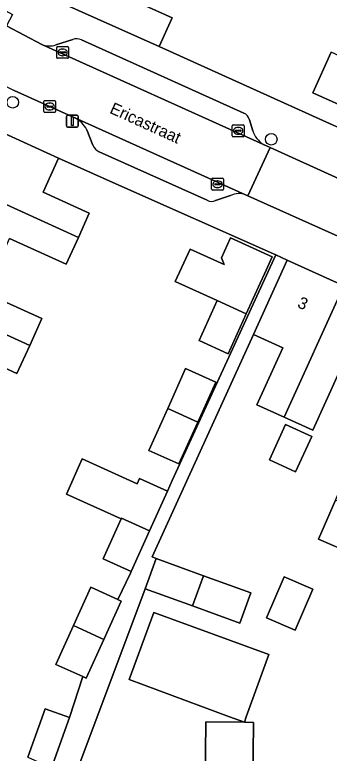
# Model space of a CAD drawing. Extents: x 161838 to 162344, y 381620 to 382160.
# Drawn here: x 162082.2 to 162108.9, y 381684.5 to 381747 of the extents above; entities that cross this region are included whole.
import ezdxf

# ---------------------------------------------------------------- set-up
doc = ezdxf.new("R2010")
doc.units = 0
for name, color, linetype in [('IMGEO_Boom', 7, 'Continuous'), ('IMGEO_Erf', 7, 'Continuous'), ('IMGEO_Kolk', 7, 'Continuous'), ('IMGEO_Lichtmast', 7, 'Continuous'), ('IMGEO_Muur', 7, 'Continuous'), ('IMGEO_Openbare_ruimte_label', 7, 'Continuous'), ('IMGEO_Pand', 7, 'Continuous'), ('IMGEO_Pand_nummerreeks', 7, 'Continuous'), ('IMGEO_Parkeervlak_open', 7, 'Continuous'), ('IMGEO_Rijbaan_lokaal_open', 7, 'Continuous'), ('IMGEO_Voetpad_open', 7, 'Continuous')]:
    doc.layers.add(name, color=color, linetype=linetype)

msp = doc.modelspace()

# ---------------------------------------------------------------- linework, layer by layer
at = {"layer": 'IMGEO_Boom'}
for centre in [(162082.036, 381739.628), (162103.955, 381736.494)]:
    msp.add_circle(centre, 0.489, dxfattribs=at)
at = {"layer": 'IMGEO_Erf'}
for points in [[(162090.511, 381749.074), (162095.561, 381746.795), (162094.462, 381744.361), (162109.199, 381737.693)], [(162109.937, 381739.317), (162107.478, 381740.434), (162109.029, 381743.87)], [(162088.658, 381698.548), (162090.95, 381697.511), (162092.017, 381699.75), (162092.078, 381699.884), (162089.708, 381700.955), (162089.797, 381701.152), (162091.243, 381704.348), (162086.595, 381706.452), (162087.939, 381709.423), (162092.588, 381707.32), (162092.79, 381707.767), (162095.158, 381706.695), (162095.567, 381707.599), (162104.332, 381726.702), (162104.139, 381726.788), (162090.772, 381732.737), (162085.927, 381734.893), (162084.615, 381732.008), (162088.528, 381730.228), (162087.601, 381728.189), (162086.563, 381725.907), (162081.771, 381728.087)], [(162079.684, 381723.498), (162084.511, 381721.303), (162083.477, 381719.029), (162082.393, 381716.646), (162077.551, 381718.849)], [(162109.694, 381716.716), (162107.482, 381711.859), (162105.035, 381712.973), (162102.742, 381714.018), (162104.938, 381718.838), (162102.44, 381719.975), (162093.858, 381701.12), (162094.204, 381700.994), (162098.21, 381699.535), (162102.216, 381698.076), (162101.28, 381695.508), (162097.275, 381696.967), (162093.269, 381698.426), (162082.012, 381668.432)], [(162083.331, 381684.161), (162084.79, 381688.265), (162086.856, 381687.521), (162087.984, 381690.984), (162085.701, 381692.017), (162087.188, 381695.302), (162088.658, 381698.548)]]:
    msp.add_lwpolyline(points, dxfattribs=at)
for points in [[(162095.816, 381724.45), (162097.067, 381727.201), (162099.956, 381725.888), (162099.736, 381726.467), (162100.504, 381728.155), (162104.03, 381726.549), (162103.369, 381725.098), (162103.005, 381724.3), (162101.828, 381721.716), (162100.289, 381718.336), (162097.831, 381719.455), (162099.37, 381722.834)], [(162096.693, 381717.076), (162099.246, 381715.924), (162097.723, 381712.549), (162096.119, 381708.994), (162093.567, 381710.146), (162095.174, 381713.708)], [(162106.017, 381708.325), (162103.793, 381709.339), (162105.159, 381712.334), (162107.383, 381711.32)], [(162110.415, 381701.575), (162110.06, 381701.727), (162107.97, 381702.62), (162109.385, 381705.932), (162110.896, 381709.468), (162113.341, 381708.423), (162111.809, 381704.837)], [(162105.979, 381694.913), (162103.552, 381695.95), (162105.041, 381699.434), (162107.468, 381698.397)], [(162101.674, 381687.113), (162100.414, 381687.58), (162091.922, 381690.727), (162093.988, 381696.402), (162103.741, 381692.849), (162101.838, 381687.567)], [(162102.347, 381676.631), (162102.339, 381675.747), (162105.346, 381675.721), (162105.285, 381668.74), (162102.278, 381668.767), (162102.257, 381666.35), (162101.562, 381666.356), (162098.216, 381666.386), (162098.219, 381666.785), (162098.299, 381675.783), (162098.306, 381676.667), (162098.398, 381687.142), (162101.674, 381687.113), (162102.439, 381687.106)]]:
    msp.add_lwpolyline(points, close=True, dxfattribs=at)
at = {"layer": 'IMGEO_Kolk'}
for p, q in [((162085.765, 381743.43), (162085.765, 381744.282)), ((162085.84, 381744.356), (162086.692, 381744.356)), ((162086.024, 381743.85), (162086.024, 381743.862)), ((162086.462, 381743.813), (162086.064, 381743.813)), ((162086.067, 381743.899), (162086.465, 381743.899)), ((162086.253, 381744.136), (162086.278, 381744.136)), ((162086.508, 381743.862), (162086.508, 381743.85)), ((162086.766, 381744.282), (162086.766, 381743.43)), ((162086.692, 381743.356), (162085.84, 381743.356)), ((162086.276, 381743.576), (162086.251, 381743.576)), ((162084.671, 381738.846), (162084.671, 381739.698)), ((162084.746, 381739.772), (162085.598, 381739.772)), ((162085.159, 381739.552), (162085.184, 381739.552)), ((162085.672, 381739.698), (162085.672, 381738.846)), ((162084.93, 381739.266), (162084.93, 381739.278)), ((162085.368, 381739.229), (162084.97, 381739.229)), ((162084.973, 381739.315), (162085.371, 381739.315)), ((162085.182, 381738.992), (162085.157, 381738.992)), ((162085.414, 381739.278), (162085.414, 381739.266)), ((162085.598, 381738.772), (162084.746, 381738.772)), ((162100.652, 381736.787), (162100.652, 381737.639)), ((162100.727, 381737.713), (162101.579, 381737.713)), ((162101.653, 381737.639), (162101.653, 381736.787)), ((162100.911, 381737.207), (162100.911, 381737.219)), ((162101.349, 381737.17), (162100.951, 381737.17)), ((162100.954, 381737.256), (162101.352, 381737.256)), ((162101.163, 381736.933), (162101.138, 381736.933)), ((162101.14, 381737.493), (162101.165, 381737.493)), ((162101.395, 381737.219), (162101.395, 381737.207)), ((162101.579, 381736.713), (162100.727, 381736.713)), ((162098.977, 381733.192), (162099.829, 381733.192)), ((162098.902, 381732.266), (162098.902, 381733.118)), ((162099.161, 381732.686), (162099.161, 381732.698)), ((162099.599, 381732.649), (162099.201, 381732.649)), ((162099.204, 381732.735), (162099.602, 381732.735)), ((162099.39, 381732.972), (162099.415, 381732.972)), ((162099.645, 381732.698), (162099.645, 381732.686)), ((162099.903, 381733.118), (162099.903, 381732.266)), ((162099.829, 381732.192), (162098.977, 381732.192)), ((162099.413, 381732.412), (162099.388, 381732.412))]:
    msp.add_line(p, q, dxfattribs=at)
for points in [[(162085.765, 381743.43), (162085.765, 381744.282)], [(162085.84, 381744.356), (162086.692, 381744.356)], [(162086.766, 381744.282), (162086.766, 381743.43)], [(162086.692, 381743.356), (162085.84, 381743.356)], [(162084.671, 381738.846), (162084.671, 381739.698)], [(162084.746, 381739.772), (162085.598, 381739.772)], [(162085.672, 381739.698), (162085.672, 381738.846)], [(162085.598, 381738.772), (162084.746, 381738.772)], [(162100.652, 381736.787), (162100.652, 381737.639)], [(162100.727, 381737.713), (162101.579, 381737.713)], [(162101.653, 381737.639), (162101.653, 381736.787)], [(162101.579, 381736.713), (162100.727, 381736.713)], [(162098.977, 381733.192), (162099.829, 381733.192)], [(162098.902, 381732.266), (162098.902, 381733.118)], [(162099.903, 381733.118), (162099.903, 381732.266)], [(162099.829, 381732.192), (162098.977, 381732.192)]]:
    msp.add_lwpolyline(points, dxfattribs=at)
for centre, radius, start, end in [((162085.842, 381744.28), 0.0765, 91.55205, 178.44795), ((162085.842, 381744.28), 0.0765, 91.55205, 178.44795), ((162086.064, 381743.859), 0.0403, 85.87752, 175.75265), ((162086.061, 381743.849), 0.0366, 178.93798, 274.71019), ((162086.465, 381743.856), 0.043, 264.86636, 352.45326), ((162086.469, 381743.861), 0.0386, 1.73085, 96.63898), ((162086.69, 381744.28), 0.0765, 1.55205, 88.44795), ((162086.69, 381744.28), 0.0765, 1.55205, 88.44795), ((162085.842, 381743.432), 0.0765, 181.55205, 268.44795), ((162085.842, 381743.432), 0.0765, 181.55205, 268.44795), ((162086.69, 381743.432), 0.0765, 271.55205, 358.44795), ((162086.69, 381743.432), 0.0765, 271.55205, 358.44795), ((162084.748, 381739.696), 0.0765, 91.55205, 178.44795), ((162084.748, 381739.696), 0.0765, 91.55205, 178.44795), ((162085.596, 381739.696), 0.0765, 1.55205, 88.44795), ((162085.596, 381739.696), 0.0765, 1.55205, 88.44795), ((162084.748, 381738.848), 0.0765, 181.55205, 268.44795), ((162084.748, 381738.848), 0.0765, 181.55205, 268.44795), ((162084.97, 381739.275), 0.0403, 85.87752, 175.75265), ((162084.967, 381739.265), 0.0366, 178.93798, 274.71019), ((162085.371, 381739.272), 0.043, 264.86636, 352.45326), ((162085.375, 381739.277), 0.0386, 1.73085, 96.63898), ((162085.596, 381738.848), 0.0765, 271.55205, 358.44795), ((162085.596, 381738.848), 0.0765, 271.55205, 358.44795), ((162100.729, 381737.637), 0.0765, 91.55205, 178.44795), ((162100.729, 381737.637), 0.0765, 91.55205, 178.44795), ((162101.577, 381737.637), 0.0765, 1.55205, 88.44795), ((162101.577, 381737.637), 0.0765, 1.55205, 88.44795), ((162100.951, 381737.216), 0.0403, 85.87752, 175.75265), ((162100.948, 381737.206), 0.0366, 178.93798, 274.71019), ((162101.352, 381737.213), 0.043, 264.86636, 352.45326), ((162101.356, 381737.218), 0.0386, 1.73085, 96.63898), ((162100.729, 381736.789), 0.0765, 181.55205, 268.44795), ((162100.729, 381736.789), 0.0765, 181.55205, 268.44795), ((162101.577, 381736.789), 0.0765, 271.55205, 358.44795), ((162101.577, 381736.789), 0.0765, 271.55205, 358.44795), ((162098.979, 381733.116), 0.0765, 91.55205, 178.44795), ((162098.979, 381733.116), 0.0765, 91.55205, 178.44795), ((162099.827, 381733.116), 0.0765, 1.55205, 88.44795), ((162099.827, 381733.116), 0.0765, 1.55205, 88.44795), ((162099.201, 381732.695), 0.0403, 85.87752, 175.75265), ((162099.198, 381732.685), 0.0366, 178.93798, 274.71019), ((162099.602, 381732.692), 0.043, 264.86636, 352.45326), ((162099.606, 381732.697), 0.0386, 1.73085, 96.63898), ((162098.979, 381732.268), 0.0765, 181.55205, 268.44795), ((162098.979, 381732.268), 0.0765, 181.55205, 268.44795), ((162099.827, 381732.268), 0.0765, 271.55205, 358.44795), ((162099.827, 381732.268), 0.0765, 271.55205, 358.44795)]:
    msp.add_arc(centre, radius, start, end, dxfattribs=at)
for centre, major_axis, ratio, start_param, end_param in [((162086.252, 381743.856), (-0.387, 0.002), 0.722429, 4.712389, 7.853982), ((162086.277, 381743.856), (-0.39, 0.002), 0.717154, 1.570796, 4.712389), ((162085.158, 381739.272), (-0.387, 0.002), 0.722429, 4.712389, 7.853982), ((162085.183, 381739.272), (-0.39, 0.002), 0.717154, 1.570796, 4.712389), ((162101.139, 381737.213), (-0.387, 0.002), 0.722429, 4.712389, 7.853982), ((162101.164, 381737.213), (-0.39, 0.002), 0.717154, 1.570796, 4.712389), ((162099.389, 381732.692), (-0.387, 0.002), 0.722429, 4.712389, 7.853982), ((162099.414, 381732.692), (-0.39, 0.002), 0.717154, 1.570796, 4.712389)]:
    msp.add_ellipse(centre, major_axis=major_axis, ratio=ratio, start_param=start_param, end_param=end_param, dxfattribs=at)
at = {"layer": 'IMGEO_Lichtmast'}
for p, q in [((162086.589, 381737.631), (162086.589, 381738.431)), ((162086.589, 381738.431), (162086.589, 381737.631)), ((162086.689, 381738.531), (162087.479, 381738.531)), ((162087.479, 381738.531), (162086.689, 381738.531)), ((162087.579, 381738.431), (162087.579, 381737.631)), ((162087.579, 381737.631), (162087.579, 381738.431)), ((162087.479, 381737.531), (162086.689, 381737.531)), ((162086.689, 381737.531), (162087.479, 381737.531))]:
    msp.add_line(p, q, dxfattribs=at)
msp.add_lwpolyline([(162087.009, 381738.406), (162087.159, 381738.406), (162087.159, 381737.656), (162087.009, 381737.656), (162087.009, 381738.406)], dxfattribs=at)
for centre, start, end in [((162086.689, 381738.431), 90, 180), ((162086.689, 381738.431), 90, 180), ((162087.479, 381738.431), 0, 90), ((162087.479, 381738.431), 360, 90), ((162086.689, 381737.631), 180, 270), ((162086.689, 381737.631), 180, 270), ((162087.479, 381737.631), 270, 0), ((162087.479, 381737.631), 270, 0)]:
    msp.add_arc(centre, 0.1, start, end, dxfattribs=at)
at = {"layer": 'IMGEO_Muur'}
for points in [[(162094.462, 381744.361), (162109.441, 381737.584)], [(162085.927, 381734.893), (162090.772, 381732.737)], [(162090.772, 381732.737), (162104.139, 381726.788)]]:
    msp.add_lwpolyline(points, dxfattribs=at)
at = {"layer": 'IMGEO_Pand'}
for points in [[(162091.62, 381751.529), (162085.748, 381754.149), (162083.874, 381750), (162083.788, 381749.81), (162086.038, 381748.793), (162085.784, 381748.23), (162094.462, 381744.361), (162095.561, 381746.795), (162090.511, 381749.074), (162090.929, 381750)], [(162109.937, 381739.317), (162111.487, 381742.753), (162109.029, 381743.87), (162107.478, 381740.434)], [(162087.601, 381728.189), (162088.528, 381730.228), (162084.615, 381732.008), (162085.927, 381734.893), (162080.942, 381737.161), (162080.663, 381736.548), (162078.267, 381737.638), (162076.306, 381733.328)], [(162087.601, 381728.189), (162076.306, 381733.328), (162074.208, 381728.716), (162080.711, 381725.757), (162081.771, 381728.087), (162086.563, 381725.907)], [(162072.147, 381724.183), (162083.477, 381719.029), (162084.511, 381721.303), (162079.684, 381723.498), (162080.711, 381725.757), (162074.208, 381728.716)], [(162103.369, 381725.098), (162104.03, 381726.549), (162100.504, 381728.155), (162099.736, 381726.467), (162099.956, 381725.888), (162097.067, 381727.201), (162095.816, 381724.45), (162099.37, 381722.834), (162101.828, 381721.716), (162103.005, 381724.3)], [(162105.035, 381712.973), (162110.102, 381724.084), (162105.307, 381726.268), (162103.234, 381721.718), (162102.44, 381719.975), (162104.938, 381718.838), (162102.742, 381714.018)], [(162072.147, 381724.183), (162070.06, 381719.595), (162076.547, 381716.643), (162077.551, 381718.849), (162082.393, 381716.646), (162083.477, 381719.029)], [(162105.035, 381712.973), (162107.482, 381711.859), (162109.694, 381716.716), (162112.052, 381715.642), (162112.829, 381717.348), (162114.846, 381721.774), (162114.902, 381721.897), (162110.102, 381724.084)], [(162101.828, 381721.716), (162099.37, 381722.834), (162097.831, 381719.455), (162100.289, 381718.336)], [(162095.174, 381713.708), (162097.723, 381712.549), (162099.246, 381715.924), (162096.693, 381717.076)], [(162095.174, 381713.708), (162093.567, 381710.146), (162096.119, 381708.994), (162097.723, 381712.549)], [(162103.793, 381709.339), (162106.017, 381708.325), (162107.383, 381711.32), (162105.159, 381712.334)], [(162095.158, 381706.695), (162092.79, 381707.767), (162092.588, 381707.32), (162087.939, 381709.423), (162086.595, 381706.452), (162091.243, 381704.348), (162091.266, 381704.399), (162093.633, 381703.323)], [(162111.809, 381704.837), (162111.457, 381704.996), (162110.669, 381705.352), (162109.385, 381705.932), (162107.97, 381702.62), (162110.06, 381701.727), (162110.415, 381701.575)], [(162093.633, 381703.323), (162091.266, 381704.399), (162091.243, 381704.348), (162089.797, 381701.152), (162089.708, 381700.955), (162092.078, 381699.884)], [(162097.275, 381696.967), (162098.21, 381699.535), (162094.204, 381700.994), (162093.269, 381698.426)], [(162097.275, 381696.967), (162101.28, 381695.508), (162102.216, 381698.076), (162098.21, 381699.535)], [(162103.552, 381695.95), (162105.979, 381694.913), (162107.468, 381698.397), (162105.041, 381699.434)], [(162090.95, 381697.511), (162088.658, 381698.548), (162087.188, 381695.302), (162089.029, 381694.464), (162089.5, 381694.25), (162089.758, 381694.133), (162091.229, 381697.385), (162091.125, 381697.432), (162090.97, 381697.502)], [(162091.922, 381690.727), (162100.414, 381687.58), (162101.674, 381687.113), (162101.838, 381687.567), (162103.741, 381692.849), (162093.988, 381696.402)], [(162089.758, 381694.133), (162089.5, 381694.25), (162089.029, 381694.464), (162087.188, 381695.302), (162085.701, 381692.017), (162087.984, 381690.984), (162088.274, 381690.853)], [(162085.32, 381683.264), (162086.856, 381687.521), (162084.79, 381688.265), (162083.331, 381684.161)], [(162101.674, 381687.113), (162098.398, 381687.142), (162098.306, 381676.667), (162098.299, 381675.783), (162102.339, 381675.747), (162102.347, 381676.631), (162102.439, 381687.106)]]:
    msp.add_lwpolyline(points, close=True, dxfattribs=at)
at = {"layer": 'IMGEO_Parkeervlak_open'}
for points in [[(162084.495, 381744.526), (162103.292, 381736.059)], [(162087.13, 381744.956), (162085.696, 381744.492)], [(162101.625, 381738.718), (162087.858, 381744.921)], [(162101.774, 381731.795), (162087.294, 381738.315)], [(162102.389, 381737.226), (162102.106, 381738.152)], [(162088.327, 381737.3), (162088.838, 381735.987)], [(162089.38, 381735.445), (162098.529, 381731.334)], [(162099.23, 381731.314), (162100.511, 381731.724)]]:
    msp.add_lwpolyline(points, dxfattribs=at)
for centre, radius, start, end in [((162085.143, 381746.191), 1.787, 248.72965, 288.02716), ((162087.453, 381744.087), 0.927, 64.10743, 110.3876), ((162086.305, 381736.276), 2.266, 26.86984, 64.13728), ((162101.225, 381737.89), 0.919, 16.52862, 64.1887), ((162104.467, 381737.901), 2.185, 197.99975, 237.46415), ((162089.775, 381736.382), 1.017, 202.86845, 247.13155), ((162098.899, 381731.995), 0.758, 240.79343, 295.93809), ((162101.223, 381730.333), 1.563, 69.34424, 117.09079)]:
    msp.add_arc(centre, radius, start, end, dxfattribs=at)
at = {"layer": 'IMGEO_Rijbaan_lokaal_open'}
msp.add_lwpolyline([(162015.372, 381769.412), (162017.318, 381768.637), (162049.197, 381754.238), (162052.77, 381752.631), (162056.86, 381750.762), (162068.214, 381745.584), (162068.985, 381745.23), (162081.324, 381741.038), (162082.15, 381740.62), (162087.294, 381738.315), (162101.774, 381731.795), (162101.956, 381731.713), (162103.87, 381735.811), (162103.292, 381736.059), (162084.495, 381744.526), (162081.506, 381746.115), (162073.51, 381750.574), (162071.642, 381751.481), (162071.089, 381751.71), (162069.847, 381752.372), (162047.793, 381762.29), (162043.964, 381764.024), (162019.542, 381775.175)], dxfattribs=at)
msp.add_lwpolyline([(162101.956, 381731.713), (162120.195, 381723.542), (162121.174, 381723.086), (162123.059, 381727.078), (162122.654, 381727.261), (162103.87, 381735.811)], close=True, dxfattribs=at)
at = {"layer": 'IMGEO_Voetpad_open'}
for points in [[(162115.037, 381735.042), (162110.328, 381737.182), (162109.441, 381737.584), (162109.199, 381737.693), (162094.462, 381744.361), (162085.784, 381748.23), (162086.038, 381748.793), (162083.788, 381749.81), (162080.79, 381751.291), (162080.545, 381750.749), (162079.471, 381748.488), (162082.026, 381747.073), (162081.506, 381746.115), (162084.495, 381744.526)], [(162085.696, 381744.492), (162087.13, 381744.956)], [(162087.858, 381744.921), (162101.625, 381738.718)], [(162087.294, 381738.315), (162082.15, 381740.62)], [(162075.442, 381738.951), (162078.267, 381737.638), (162080.663, 381736.548), (162080.942, 381737.161), (162085.927, 381734.893), (162090.772, 381732.737), (162104.139, 381726.788), (162104.332, 381726.702), (162105.307, 381726.268), (162110.102, 381724.084), (162114.902, 381721.897), (162114.846, 381721.774), (162116.134, 381721.209), (162122.299, 381718.4), (162123.45, 381717.876), (162132.746, 381713.736), (162141.842, 381709.627), (162144.891, 381708.096)], [(162102.106, 381738.152), (162102.389, 381737.226)], [(162088.838, 381735.987), (162088.327, 381737.3)], [(162103.292, 381736.059), (162103.87, 381735.811), (162122.654, 381727.261)], [(162098.529, 381731.334), (162089.38, 381735.445)], [(162100.511, 381731.724), (162099.23, 381731.314)], [(162101.956, 381731.713), (162101.774, 381731.795)], [(162125.376, 381721.164), (162124.741, 381721.45), (162124.241, 381720.486), (162119.809, 381722.495), (162120.195, 381723.542), (162101.956, 381731.713)], [(162093.269, 381698.426), (162094.204, 381700.994), (162093.858, 381701.12), (162102.44, 381719.975), (162103.234, 381721.718), (162105.307, 381726.268), (162104.332, 381726.702), (162095.567, 381707.599), (162095.158, 381706.695), (162093.633, 381703.323), (162092.078, 381699.884), (162092.017, 381699.75), (162090.95, 381697.511), (162090.97, 381697.502), (162091.125, 381697.432), (162091.229, 381697.385), (162089.758, 381694.133), (162088.274, 381690.853), (162087.984, 381690.984), (162086.856, 381687.521), (162085.32, 381683.264)], [(162048.665, 381666.475), (162047.965, 381661.765), (162053.763, 381661.652), (162057.625, 381661.577), (162060.063, 381661.514), (162064.391, 381661.46), (162068.379, 381661.411), (162072.739, 381661.332), (162076.93, 381661.252), (162078.735, 381661.272), (162079.661, 381662.314), (162081.862, 381661.656), (162083.454, 381663.134), (162082.012, 381668.432), (162093.269, 381698.426)]]:
    msp.add_lwpolyline(points, dxfattribs=at)
for centre, radius, start, end in [((162085.143, 381746.191), 1.787, 248.72965, 288.02716), ((162087.453, 381744.087), 0.927, 64.10743, 110.3876), ((162086.305, 381736.276), 2.266, 26.86984, 64.13728), ((162101.225, 381737.89), 0.919, 16.52862, 64.1887), ((162104.467, 381737.901), 2.185, 197.99975, 237.46415), ((162089.775, 381736.382), 1.017, 202.86845, 247.13155), ((162098.899, 381731.995), 0.758, 240.79343, 295.93809), ((162101.223, 381730.333), 1.563, 69.34424, 117.09079)]:
    msp.add_arc(centre, radius, start, end, dxfattribs=at)

# ---------------------------------------------------------------- texts
at = {"layer": 'IMGEO_Openbare_ruimte_label'}
msp.add_text('Ericastraat', height=1, rotation=335.53707, dxfattribs=at).set_placement((162090.184, 381738.752))
at = {"layer": 'IMGEO_Pand_nummerreeks'}
msp.add_text('3', height=1, rotation=335.50837, dxfattribs=at).set_placement((162106.096, 381722.305))

doc.saveas('drawing.dxf')
